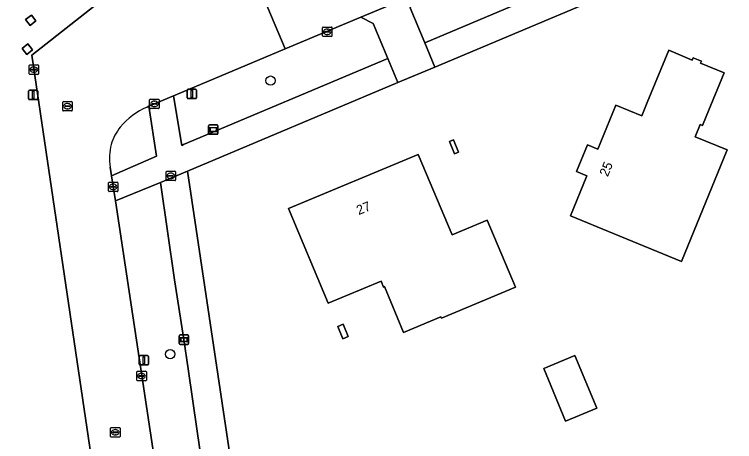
# Model space of a CAD drawing. Extents: x 162417 to 163722, y 384268 to 385417.
# Drawn here: x 163157.7 to 163233.6, y 384866.4 to 384911.4 of the extents above; entities that cross this region are included whole.
import ezdxf

# ---------------------------------------------------------------- set-up
doc = ezdxf.new("R2010")
doc.units = 0
for name, color, linetype in [('IMGEO_Berm_groen', 7, 'Continuous'), ('IMGEO_Boom', 7, 'Continuous'), ('IMGEO_Brandkraan', 7, 'Continuous'), ('IMGEO_Erf', 7, 'Continuous'), ('IMGEO_Groenvoorziening', 7, 'Continuous'), ('IMGEO_Kolk', 7, 'Continuous'), ('IMGEO_Lichtmast', 7, 'Continuous'), ('IMGEO_Pand', 7, 'Continuous'), ('IMGEO_Pand_nummerreeks', 7, 'Continuous'), ('IMGEO_Rijbaan_lokaal_gesloten', 7, 'Continuous'), ('IMGEO_Rioolput', 7, 'Continuous'), ('IMGEO_Voetpad_open', 7, 'Continuous'), ('IMGEO_Wegwijzer', 7, 'Continuous')]:
    doc.layers.add(name, color=color, linetype=linetype)

msp = doc.modelspace()

# ---------------------------------------------------------------- linework, layer by layer
at = {"layer": 'IMGEO_Berm_groen'}
msp.add_lwpolyline([(163177.654, 384862.939), (163176.986, 384867.512), (163176.027, 384874.074), (163175.599, 384877.142), (163174.611, 384883.435), (163173.131, 384893.686), (163168.375, 384891.762), (163181.052, 384807.665)], dxfattribs=at)
at = {"layer": 'IMGEO_Boom'}
for centre in [(163184.731, 384904.423), (163174.147, 384875.612)]:
    msp.add_circle(centre, 0.489, dxfattribs=at)
at = {"layer": 'IMGEO_Brandkraan'}
for p, q in [((163173.795, 384894.892), (163174.647, 384894.892)), ((163173.72, 384893.966), (163173.72, 384894.818)), ((163173.979, 384894.386), (163173.979, 384894.398)), ((163174.417, 384894.349), (163174.019, 384894.349)), ((163174.022, 384894.435), (163174.42, 384894.435)), ((163174.231, 384894.112), (163174.206, 384894.112)), ((163174.208, 384894.672), (163174.233, 384894.672)), ((163174.463, 384894.398), (163174.463, 384894.386)), ((163174.721, 384894.818), (163174.721, 384893.966)), ((163174.647, 384893.892), (163173.795, 384893.892))]:
    msp.add_line(p, q, dxfattribs=at)
for points in [[(163173.795, 384894.892), (163174.647, 384894.892)], [(163173.72, 384893.966), (163173.72, 384894.818)], [(163174.721, 384894.818), (163174.721, 384893.966)], [(163174.647, 384893.892), (163173.795, 384893.892)]]:
    msp.add_lwpolyline(points, dxfattribs=at)
for centre, radius, start, end in [((163173.797, 384894.816), 0.0765, 91.55205, 178.44795), ((163173.797, 384894.816), 0.0765, 91.55205, 178.44795), ((163174.645, 384894.816), 0.0765, 1.55205, 88.44795), ((163174.645, 384894.816), 0.0765, 1.55205, 88.44795), ((163174.019, 384894.395), 0.0403, 85.87752, 175.75265), ((163174.016, 384894.385), 0.0366, 178.93798, 274.71019), ((163174.42, 384894.392), 0.043, 264.86636, 352.45326), ((163174.424, 384894.397), 0.0386, 1.73085, 96.63898), ((163173.797, 384893.968), 0.0765, 181.55205, 268.44795), ((163173.797, 384893.968), 0.0765, 181.55205, 268.44795), ((163174.645, 384893.968), 0.0765, 271.55205, 358.44795), ((163174.645, 384893.968), 0.0765, 271.55205, 358.44795)]:
    msp.add_arc(centre, radius, start, end, dxfattribs=at)
for centre, major_axis, ratio, start_param, end_param in [((163174.207, 384894.392), (-0.387, 0.002), 0.722429, 4.712389, 7.853982), ((163174.232, 384894.392), (-0.39, 0.002), 0.717154, 1.570796, 4.712389)]:
    msp.add_ellipse(centre, major_axis=major_axis, ratio=ratio, start_param=start_param, end_param=end_param, dxfattribs=at)
at = {"layer": 'IMGEO_Erf'}
msp.add_lwpolyline([(163355.108, 384922.849), (163338.205, 384963.202), (163332.037, 384960.636), (163331.845, 384960.556), (163328.115, 384959.004), (163309.804, 384951.385), (163305.952, 384950.098), (163301.519, 384948.918), (163287.113, 384942.953), (163279.759, 384939.573), (163273.176, 384936.418), (163263.164, 384931.62), (163230.9, 384918.02), (163227.943, 384916.773), (163202.03, 384905.85), (163198.14, 384904.21), (163175.984, 384894.871), (163189.317, 384805.604)], dxfattribs=at)
for points in [[(163159.564, 384907.094), (163168.293, 384913.998), (163151.904, 384951.836), (163097.149, 384943.131), (163103.623, 384899.24), (163109.03, 384862.7), (163116.803, 384810.173), (163172.668, 384818.516)], [(163160.001, 384910.711), (163159.521, 384911.33), (163158.908, 384910.853), (163159.388, 384910.235)], [(163158.908, 384910.853), (163159.521, 384911.33), (163160.001, 384910.711), (163159.388, 384910.235)], [(163159.639, 384907.669), (163159.149, 384908.282), (163158.541, 384907.796), (163159.031, 384907.183)], [(163158.541, 384907.796), (163159.149, 384908.282), (163159.639, 384907.669), (163159.031, 384907.183)], [(163219.212, 384897.218), (163221.117, 384901.842), (163223.845, 384900.717), (163224.418, 384902.108), (163226.688, 384907.618), (163229.166, 384906.596), (163229.267, 384906.841), (163230.138, 384906.482), (163230.053, 384906.278), (163232.528, 384905.258), (163230.623, 384900.636), (163230.24, 384899.706), (163230.013, 384899.799), (163229.485, 384898.518), (163232.864, 384897.126), (163228.023, 384885.379), (163220.95, 384888.293), (163216.327, 384890.198), (163218.057, 384894.399), (163216.97, 384894.847), (163218.13, 384897.663)], [(163204.002, 384898.194), (163204.551, 384896.897), (163204.113, 384896.72), (163203.576, 384898.018)], [(163207.571, 384889.719), (163210.531, 384882.668), (163202.73, 384879.41), (163202.676, 384879.54), (163198.744, 384877.898), (163196.747, 384882.732), (163196.636, 384882.685), (163196.371, 384883.306), (163190.802, 384880.971), (163186.632, 384890.943), (163200.299, 384896.652), (163203.868, 384888.194)], [(163192.363, 384878.77), (163192.905, 384877.463), (163192.36, 384877.237), (163191.817, 384878.544)], [(163216.811, 384875.464), (163219.102, 384869.919), (163215.802, 384868.554), (163213.511, 384874.1)]]:
    msp.add_lwpolyline(points, close=True, dxfattribs=at)
at = {"layer": 'IMGEO_Groenvoorziening'}
for points in [[(163200.97, 384908.409), (163226.912, 384919.359), (163225.352, 384923.271), (163224.3, 384923.826), (163200.018, 384913.546), (163199.446, 384912.087)], [(163197.077, 384906.757), (163195.54, 384910.438), (163194.231, 384911.102), (163186.272, 384907.759), (163174.684, 384902.892), (163174.507, 384902.818), (163175.359, 384897.603), (163175.545, 384897.682)]]:
    msp.add_lwpolyline(points, close=True, dxfattribs=at)
for points in [[(163167.833, 384895.326), (163167.974, 384894.412), (163172.706, 384896.469), (163171.894, 384901.719)], [(163171.894, 384901.719), (163171.712, 384901.639)]]:
    msp.add_lwpolyline(points, dxfattribs=at)
for centre, radius, start, end in [((163174.631, 384894.765), 7.468, 113.00878, 140.25543), ((163172.938, 384896.273), 5.202, 141.10387, 164.00436), ((163173.401, 384896.276), 5.649, 165.32083, 189.67709)]:
    msp.add_arc(centre, radius, start, end, dxfattribs=at)
at = {"layer": 'IMGEO_Kolk'}
for p, q in [((163190.276, 384910.068), (163191.128, 384910.068)), ((163190.201, 384909.142), (163190.201, 384909.994)), ((163190.46, 384909.562), (163190.46, 384909.574)), ((163190.898, 384909.525), (163190.5, 384909.525)), ((163190.503, 384909.611), (163190.901, 384909.611)), ((163190.712, 384909.288), (163190.687, 384909.288)), ((163190.689, 384909.848), (163190.714, 384909.848)), ((163190.944, 384909.574), (163190.944, 384909.562)), ((163191.202, 384909.994), (163191.202, 384909.142)), ((163191.128, 384909.068), (163190.276, 384909.068)), ((163159.282, 384905.156), (163159.282, 384906.008)), ((163159.357, 384906.082), (163160.209, 384906.082)), ((163159.541, 384905.576), (163159.541, 384905.588)), ((163159.979, 384905.539), (163159.581, 384905.539)), ((163159.584, 384905.625), (163159.982, 384905.625)), ((163159.77, 384905.862), (163159.795, 384905.862)), ((163160.025, 384905.588), (163160.025, 384905.576)), ((163160.283, 384906.008), (163160.283, 384905.156)), ((163160.209, 384905.082), (163159.357, 384905.082)), ((163159.793, 384905.302), (163159.768, 384905.302)), ((163172.058, 384902.474), (163172.91, 384902.474)), ((163171.983, 384901.548), (163171.983, 384902.4)), ((163172.242, 384901.968), (163172.242, 384901.98)), ((163172.68, 384901.931), (163172.282, 384901.931)), ((163172.285, 384902.017), (163172.683, 384902.017)), ((163172.494, 384901.694), (163172.469, 384901.694)), ((163172.471, 384902.254), (163172.496, 384902.254)), ((163172.726, 384901.98), (163172.726, 384901.968)), ((163172.984, 384902.4), (163172.984, 384901.548)), ((163172.91, 384901.474), (163172.058, 384901.474)), ((163167.645, 384892.808), (163167.645, 384893.66)), ((163167.72, 384893.734), (163168.572, 384893.734)), ((163168.133, 384893.514), (163168.158, 384893.514)), ((163168.646, 384893.66), (163168.646, 384892.808)), ((163168.572, 384892.734), (163167.72, 384892.734)), ((163167.904, 384893.228), (163167.904, 384893.24)), ((163168.342, 384893.191), (163167.944, 384893.191)), ((163167.947, 384893.277), (163168.345, 384893.277)), ((163168.156, 384892.954), (163168.131, 384892.954)), ((163168.388, 384893.24), (163168.388, 384893.228)), ((163170.636, 384872.888), (163170.636, 384873.74)), ((163170.711, 384873.814), (163171.563, 384873.814)), ((163171.637, 384873.74), (163171.637, 384872.888)), ((163170.895, 384873.308), (163170.895, 384873.32)), ((163171.333, 384873.271), (163170.935, 384873.271)), ((163170.938, 384873.357), (163171.336, 384873.357)), ((163171.147, 384873.034), (163171.122, 384873.034)), ((163171.124, 384873.594), (163171.149, 384873.594)), ((163171.379, 384873.32), (163171.379, 384873.308)), ((163171.563, 384872.814), (163170.711, 384872.814))]:
    msp.add_line(p, q, dxfattribs=at)
for points in [[(163190.276, 384910.068), (163191.128, 384910.068)], [(163190.201, 384909.142), (163190.201, 384909.994)], [(163191.202, 384909.994), (163191.202, 384909.142)], [(163191.128, 384909.068), (163190.276, 384909.068)], [(163159.282, 384905.156), (163159.282, 384906.008)], [(163159.357, 384906.082), (163160.209, 384906.082)], [(163160.283, 384906.008), (163160.283, 384905.156)], [(163160.209, 384905.082), (163159.357, 384905.082)], [(163172.058, 384902.474), (163172.91, 384902.474)], [(163171.983, 384901.548), (163171.983, 384902.4)], [(163172.984, 384902.4), (163172.984, 384901.548)], [(163172.91, 384901.474), (163172.058, 384901.474)], [(163167.645, 384892.808), (163167.645, 384893.66)], [(163167.72, 384893.734), (163168.572, 384893.734)], [(163168.646, 384893.66), (163168.646, 384892.808)], [(163168.572, 384892.734), (163167.72, 384892.734)], [(163170.636, 384872.888), (163170.636, 384873.74)], [(163170.711, 384873.814), (163171.563, 384873.814)], [(163171.637, 384873.74), (163171.637, 384872.888)], [(163171.563, 384872.814), (163170.711, 384872.814)]]:
    msp.add_lwpolyline(points, dxfattribs=at)
for centre, radius, start, end in [((163190.278, 384909.992), 0.0765, 91.55205, 178.44795), ((163190.278, 384909.992), 0.0765, 91.55205, 178.44795), ((163191.126, 384909.992), 0.0765, 1.55205, 88.44795), ((163191.126, 384909.992), 0.0765, 1.55205, 88.44795), ((163190.5, 384909.571), 0.0403, 85.87752, 175.75265), ((163190.497, 384909.561), 0.0366, 178.93798, 274.71019), ((163190.901, 384909.568), 0.043, 264.86636, 352.45326), ((163190.905, 384909.573), 0.0386, 1.73085, 96.63898), ((163190.278, 384909.144), 0.0765, 181.55205, 268.44795), ((163190.278, 384909.144), 0.0765, 181.55205, 268.44795), ((163191.126, 384909.144), 0.0765, 271.55205, 358.44795), ((163191.126, 384909.144), 0.0765, 271.55205, 358.44795), ((163159.359, 384906.006), 0.0765, 91.55205, 178.44795), ((163159.359, 384906.006), 0.0765, 91.55205, 178.44795), ((163159.581, 384905.585), 0.0403, 85.87752, 175.75265), ((163159.578, 384905.575), 0.0366, 178.93798, 274.71019), ((163159.982, 384905.582), 0.043, 264.86636, 352.45326), ((163159.986, 384905.587), 0.0386, 1.73085, 96.63898), ((163160.207, 384906.006), 0.0765, 1.55205, 88.44795), ((163160.207, 384906.006), 0.0765, 1.55205, 88.44795), ((163159.359, 384905.158), 0.0765, 181.55205, 268.44795), ((163159.359, 384905.158), 0.0765, 181.55205, 268.44795), ((163160.207, 384905.158), 0.0765, 271.55205, 358.44795), ((163160.207, 384905.158), 0.0765, 271.55205, 358.44795), ((163172.06, 384902.398), 0.0765, 91.55205, 178.44795), ((163172.06, 384902.398), 0.0765, 91.55205, 178.44795), ((163172.908, 384902.398), 0.0765, 1.55205, 88.44795), ((163172.908, 384902.398), 0.0765, 1.55205, 88.44795), ((163172.282, 384901.977), 0.0403, 85.87752, 175.75265), ((163172.279, 384901.967), 0.0366, 178.93798, 274.71019), ((163172.683, 384901.974), 0.043, 264.86636, 352.45326), ((163172.687, 384901.979), 0.0386, 1.73085, 96.63898), ((163172.06, 384901.55), 0.0765, 181.55205, 268.44795), ((163172.06, 384901.55), 0.0765, 181.55205, 268.44795), ((163172.908, 384901.55), 0.0765, 271.55205, 358.44795), ((163172.908, 384901.55), 0.0765, 271.55205, 358.44795), ((163167.722, 384893.658), 0.0765, 91.55205, 178.44795), ((163167.722, 384893.658), 0.0765, 91.55205, 178.44795), ((163168.57, 384893.658), 0.0765, 1.55205, 88.44795), ((163168.57, 384893.658), 0.0765, 1.55205, 88.44795), ((163167.722, 384892.81), 0.0765, 181.55205, 268.44795), ((163167.722, 384892.81), 0.0765, 181.55205, 268.44795), ((163167.944, 384893.237), 0.0403, 85.87752, 175.75265), ((163167.941, 384893.227), 0.0366, 178.93798, 274.71019), ((163168.345, 384893.234), 0.043, 264.86636, 352.45326), ((163168.349, 384893.239), 0.0386, 1.73085, 96.63898), ((163168.57, 384892.81), 0.0765, 271.55205, 358.44795), ((163168.57, 384892.81), 0.0765, 271.55205, 358.44795), ((163170.713, 384873.738), 0.0765, 91.55205, 178.44795), ((163170.713, 384873.738), 0.0765, 91.55205, 178.44795), ((163171.561, 384873.738), 0.0765, 1.55205, 88.44795), ((163171.561, 384873.738), 0.0765, 1.55205, 88.44795), ((163170.713, 384872.89), 0.0765, 181.55205, 268.44795), ((163170.713, 384872.89), 0.0765, 181.55205, 268.44795), ((163170.935, 384873.317), 0.0403, 85.87752, 175.75265), ((163170.932, 384873.307), 0.0366, 178.93798, 274.71019), ((163171.336, 384873.314), 0.043, 264.86636, 352.45326), ((163171.34, 384873.319), 0.0386, 1.73085, 96.63898), ((163171.561, 384872.89), 0.0765, 271.55205, 358.44795), ((163171.561, 384872.89), 0.0765, 271.55205, 358.44795)]:
    msp.add_arc(centre, radius, start, end, dxfattribs=at)
for centre, major_axis, ratio, start_param, end_param in [((163190.688, 384909.568), (-0.387, 0.002), 0.722429, 4.712389, 7.853982), ((163190.713, 384909.568), (-0.39, 0.002), 0.717154, 1.570796, 4.712389), ((163159.769, 384905.582), (-0.387, 0.002), 0.722429, 4.712389, 7.853982), ((163159.794, 384905.582), (-0.39, 0.002), 0.717154, 1.570796, 4.712389), ((163172.47, 384901.974), (-0.387, 0.002), 0.722429, 4.712389, 7.853982), ((163172.495, 384901.974), (-0.39, 0.002), 0.717154, 1.570796, 4.712389), ((163168.132, 384893.234), (-0.387, 0.002), 0.722429, 4.712389, 7.853982), ((163168.157, 384893.234), (-0.39, 0.002), 0.717154, 1.570796, 4.712389), ((163171.123, 384873.314), (-0.387, 0.002), 0.722429, 4.712389, 7.853982), ((163171.148, 384873.314), (-0.39, 0.002), 0.717154, 1.570796, 4.712389)]:
    msp.add_ellipse(centre, major_axis=major_axis, ratio=ratio, start_param=start_param, end_param=end_param, dxfattribs=at)
at = {"layer": 'IMGEO_Lichtmast'}
for p, q in [((163159.221, 384902.524), (163159.221, 384903.324)), ((163159.221, 384903.324), (163159.221, 384902.524)), ((163159.321, 384903.424), (163160.111, 384903.424)), ((163160.111, 384903.424), (163159.321, 384903.424)), ((163160.211, 384903.324), (163160.211, 384902.524)), ((163160.211, 384902.524), (163160.211, 384903.324)), ((163175.937, 384902.627), (163175.937, 384903.427)), ((163175.937, 384903.427), (163175.937, 384902.627)), ((163176.037, 384903.527), (163176.827, 384903.527)), ((163176.827, 384903.527), (163176.037, 384903.527)), ((163176.927, 384903.427), (163176.927, 384902.627)), ((163176.927, 384902.627), (163176.927, 384903.427)), ((163176.827, 384902.527), (163176.037, 384902.527)), ((163176.037, 384902.527), (163176.827, 384902.527)), ((163160.111, 384902.424), (163159.321, 384902.424)), ((163159.321, 384902.424), (163160.111, 384902.424)), ((163170.877, 384874.574), (163170.877, 384875.374)), ((163170.877, 384875.374), (163170.877, 384874.574)), ((163170.977, 384875.474), (163171.767, 384875.474)), ((163171.767, 384875.474), (163170.977, 384875.474)), ((163171.867, 384875.374), (163171.867, 384874.574)), ((163171.867, 384874.574), (163171.867, 384875.374)), ((163171.767, 384874.474), (163170.977, 384874.474)), ((163170.977, 384874.474), (163171.767, 384874.474))]:
    msp.add_line(p, q, dxfattribs=at)
for points in [[(163159.641, 384903.299), (163159.791, 384903.299), (163159.791, 384902.549), (163159.641, 384902.549), (163159.641, 384903.299)], [(163176.357, 384903.402), (163176.507, 384903.402), (163176.507, 384902.652), (163176.357, 384902.652), (163176.357, 384903.402)], [(163171.297, 384875.349), (163171.447, 384875.349), (163171.447, 384874.599), (163171.297, 384874.599), (163171.297, 384875.349)]]:
    msp.add_lwpolyline(points, dxfattribs=at)
for centre, start, end in [((163159.321, 384903.324), 90, 180), ((163159.321, 384903.324), 90, 180), ((163160.111, 384903.324), 0, 90), ((163160.111, 384903.324), 360, 90), ((163176.037, 384903.427), 90, 180), ((163176.037, 384903.427), 90, 180), ((163176.827, 384903.427), 0, 90), ((163176.827, 384903.427), 360, 90), ((163159.321, 384902.524), 180, 270), ((163159.321, 384902.524), 180, 270), ((163160.111, 384902.524), 270, 0), ((163160.111, 384902.524), 270, 0), ((163176.037, 384902.627), 180, 270), ((163176.037, 384902.627), 180, 270), ((163176.827, 384902.627), 270, 0), ((163176.827, 384902.627), 270, 0), ((163170.977, 384875.374), 90, 180), ((163170.977, 384875.374), 90, 180), ((163171.767, 384875.374), 0, 90), ((163171.767, 384875.374), 360, 90), ((163170.977, 384874.574), 180, 270), ((163170.977, 384874.574), 180, 270), ((163171.767, 384874.574), 270, 0), ((163171.767, 384874.574), 270, 0)]:
    msp.add_arc(centre, 0.1, start, end, dxfattribs=at)
at = {"layer": 'IMGEO_Pand'}
for points in [[(163219.212, 384897.218), (163218.13, 384897.663), (163216.97, 384894.847), (163218.057, 384894.399), (163216.327, 384890.198), (163220.95, 384888.293), (163228.023, 384885.379), (163232.864, 384897.126), (163229.485, 384898.518), (163230.013, 384899.799), (163230.24, 384899.706), (163230.623, 384900.636), (163232.528, 384905.258), (163230.053, 384906.278), (163230.138, 384906.482), (163229.267, 384906.841), (163229.166, 384906.596), (163226.688, 384907.618), (163224.418, 384902.108), (163223.845, 384900.717), (163221.117, 384901.842)], [(163204.002, 384898.194), (163203.576, 384898.018), (163204.113, 384896.72), (163204.551, 384896.897)], [(163207.571, 384889.719), (163203.868, 384888.194), (163200.299, 384896.652), (163186.632, 384890.943), (163190.802, 384880.971), (163196.371, 384883.306), (163196.636, 384882.685), (163196.747, 384882.732), (163198.744, 384877.898), (163202.676, 384879.54), (163202.73, 384879.41), (163210.531, 384882.668)], [(163192.363, 384878.77), (163191.817, 384878.544), (163192.36, 384877.237), (163192.905, 384877.463)], [(163216.811, 384875.464), (163213.511, 384874.1), (163215.802, 384868.554), (163219.102, 384869.919)]]:
    msp.add_lwpolyline(points, close=True, dxfattribs=at)
at = {"layer": 'IMGEO_Rijbaan_lokaal_gesloten'}
for points in [[(163337.564, 384978.789), (163336.54, 384978.154), (163336.199, 384978.01), (163333.911, 384977.041), (163328.962, 384974.963), (163183.667, 384913.961), (163186.272, 384907.759), (163194.231, 384911.102), (163200.018, 384913.546), (163224.3, 384923.826)], [(163186.272, 384907.759), (163183.667, 384913.961), (163175.758, 384919.851), (163175.467, 384919.624), (163173.108, 384917.782), (163170.764, 384915.952), (163168.293, 384913.998), (163159.564, 384907.094), (163172.668, 384818.516)], [(163171.712, 384901.639), (163171.894, 384901.719), (163172.075, 384901.798), (163174.507, 384902.818), (163174.684, 384902.892), (163186.272, 384907.759)], [(163181.052, 384807.665), (163168.375, 384891.762), (163167.974, 384894.412), (163167.833, 384895.326)]]:
    msp.add_lwpolyline(points, dxfattribs=at)
for centre, radius, start, end in [((163174.631, 384894.765), 7.468, 113.00878, 140.25543), ((163172.938, 384896.273), 5.202, 141.10387, 164.00436), ((163173.401, 384896.276), 5.649, 165.32083, 189.67709)]:
    msp.add_arc(centre, radius, start, end, dxfattribs=at)
at = {"layer": 'IMGEO_Rioolput'}
for p, q in [((163162.823, 384901.302), (163162.823, 384902.154)), ((163162.898, 384902.228), (163163.75, 384902.228)), ((163163.082, 384901.722), (163163.082, 384901.734)), ((163163.52, 384901.685), (163163.122, 384901.685)), ((163163.125, 384901.771), (163163.523, 384901.771)), ((163163.311, 384902.008), (163163.336, 384902.008)), ((163163.566, 384901.734), (163163.566, 384901.722)), ((163163.824, 384902.154), (163163.824, 384901.302)), ((163163.75, 384901.228), (163162.898, 384901.228)), ((163163.334, 384901.448), (163163.309, 384901.448)), ((163167.865, 384866.958), (163167.865, 384867.81)), ((163167.94, 384867.884), (163168.792, 384867.884)), ((163168.353, 384867.664), (163168.378, 384867.664)), ((163168.866, 384867.81), (163168.866, 384866.958)), ((163168.792, 384866.884), (163167.94, 384866.884)), ((163168.124, 384867.378), (163168.124, 384867.39)), ((163168.562, 384867.341), (163168.164, 384867.341)), ((163168.167, 384867.427), (163168.565, 384867.427)), ((163168.376, 384867.104), (163168.351, 384867.104)), ((163168.608, 384867.39), (163168.608, 384867.378))]:
    msp.add_line(p, q, dxfattribs=at)
for points in [[(163162.823, 384901.302), (163162.823, 384902.154)], [(163162.898, 384902.228), (163163.75, 384902.228)], [(163163.824, 384902.154), (163163.824, 384901.302)], [(163163.75, 384901.228), (163162.898, 384901.228)], [(163167.865, 384866.958), (163167.865, 384867.81)], [(163167.94, 384867.884), (163168.792, 384867.884)], [(163168.866, 384867.81), (163168.866, 384866.958)], [(163168.792, 384866.884), (163167.94, 384866.884)]]:
    msp.add_lwpolyline(points, dxfattribs=at)
for centre, radius, start, end in [((163162.9, 384902.152), 0.0765, 91.55205, 178.44795), ((163162.9, 384902.152), 0.0765, 91.55205, 178.44795), ((163163.122, 384901.731), 0.0403, 85.87752, 175.75265), ((163163.119, 384901.721), 0.0366, 178.93798, 274.71019), ((163163.523, 384901.728), 0.043, 264.86636, 352.45326), ((163163.527, 384901.733), 0.0386, 1.73085, 96.63898), ((163163.748, 384902.152), 0.0765, 1.55205, 88.44795), ((163163.748, 384902.152), 0.0765, 1.55205, 88.44795), ((163162.9, 384901.304), 0.0765, 181.55205, 268.44795), ((163162.9, 384901.304), 0.0765, 181.55205, 268.44795), ((163163.748, 384901.304), 0.0765, 271.55205, 358.44795), ((163163.748, 384901.304), 0.0765, 271.55205, 358.44795), ((163167.942, 384867.808), 0.0765, 91.55205, 178.44795), ((163167.942, 384867.808), 0.0765, 91.55205, 178.44795), ((163168.79, 384867.808), 0.0765, 1.55205, 88.44795), ((163168.79, 384867.808), 0.0765, 1.55205, 88.44795), ((163167.942, 384866.96), 0.0765, 181.55205, 268.44795), ((163167.942, 384866.96), 0.0765, 181.55205, 268.44795), ((163168.164, 384867.387), 0.0403, 85.87752, 175.75265), ((163168.161, 384867.377), 0.0366, 178.93798, 274.71019), ((163168.565, 384867.384), 0.043, 264.86636, 352.45326), ((163168.569, 384867.389), 0.0386, 1.73085, 96.63898), ((163168.79, 384866.96), 0.0765, 271.55205, 358.44795), ((163168.79, 384866.96), 0.0765, 271.55205, 358.44795)]:
    msp.add_arc(centre, radius, start, end, dxfattribs=at)
for centre, major_axis, ratio, start_param, end_param in [((163163.31, 384901.728), (-0.387, 0.002), 0.722429, 4.712389, 7.853982), ((163163.335, 384901.728), (-0.39, 0.002), 0.717154, 1.570796, 4.712389), ((163168.352, 384867.384), (-0.387, 0.002), 0.722429, 4.712389, 7.853982), ((163168.377, 384867.384), (-0.39, 0.002), 0.717154, 1.570796, 4.712389)]:
    msp.add_ellipse(centre, major_axis=major_axis, ratio=ratio, start_param=start_param, end_param=end_param, dxfattribs=at)
at = {"layer": 'IMGEO_Voetpad_open'}
for points in [[(163202.03, 384905.85), (163227.943, 384916.773), (163226.912, 384919.359), (163200.97, 384908.409)], [(163200.97, 384908.409), (163199.446, 384912.087), (163200.018, 384913.546), (163194.231, 384911.102), (163195.54, 384910.438), (163197.077, 384906.757), (163198.14, 384904.21), (163202.03, 384905.85)], [(163198.14, 384904.21), (163197.077, 384906.757), (163175.545, 384897.682), (163175.359, 384897.603), (163174.507, 384902.818), (163172.075, 384901.798), (163171.894, 384901.719), (163172.706, 384896.469), (163167.974, 384894.412), (163168.375, 384891.762), (163173.131, 384893.686), (163175.984, 384894.871)], [(163175.984, 384894.871), (163173.131, 384893.686), (163174.611, 384883.435), (163175.599, 384877.142), (163176.027, 384874.074), (163176.986, 384867.512), (163177.654, 384862.939), (163181.731, 384836.256), (163185.853, 384808.72), (163186.458, 384804.456), (163186.712, 384804.512), (163189.317, 384805.604)]]:
    msp.add_lwpolyline(points, close=True, dxfattribs=at)
at = {"layer": 'IMGEO_Wegwijzer'}
for p, q in [((163178.194, 384898.868), (163178.194, 384899.668)), ((163178.194, 384899.668), (163178.194, 384898.868)), ((163178.294, 384899.768), (163179.084, 384899.768)), ((163179.084, 384899.768), (163178.294, 384899.768)), ((163179.184, 384899.668), (163179.184, 384898.868)), ((163179.184, 384898.868), (163179.184, 384899.668)), ((163179.084, 384898.768), (163178.294, 384898.768)), ((163178.294, 384898.768), (163179.084, 384898.768)), ((163175.104, 384876.742), (163175.104, 384877.542)), ((163175.104, 384877.542), (163175.104, 384876.742)), ((163175.204, 384877.642), (163175.994, 384877.642)), ((163175.994, 384877.642), (163175.204, 384877.642)), ((163176.094, 384877.542), (163176.094, 384876.742)), ((163176.094, 384876.742), (163176.094, 384877.542)), ((163175.994, 384876.642), (163175.204, 384876.642)), ((163175.204, 384876.642), (163175.994, 384876.642))]:
    msp.add_line(p, q, dxfattribs=at)
for points in [[(163178.295, 384899.5), (163179.083, 384899.5), (163179.083, 384899.036), (163178.295, 384899.036), (163178.295, 384899.5)], [(163178.36, 384899.435), (163178.36, 384899.101), (163179.018, 384899.101), (163179.018, 384899.435), (163178.36, 384899.435)], [(163175.205, 384877.374), (163175.993, 384877.374), (163175.993, 384876.91), (163175.205, 384876.91), (163175.205, 384877.374)], [(163175.27, 384877.309), (163175.27, 384876.975), (163175.928, 384876.975), (163175.928, 384877.309), (163175.27, 384877.309)]]:
    msp.add_lwpolyline(points, dxfattribs=at)
for centre, start, end in [((163178.294, 384899.668), 90, 180), ((163178.294, 384899.668), 90, 180), ((163179.084, 384899.668), 0, 90), ((163179.084, 384899.668), 360, 90), ((163178.294, 384898.868), 180, 270), ((163178.294, 384898.868), 180, 270), ((163179.084, 384898.868), 270, 0), ((163179.084, 384898.868), 270, 0), ((163175.204, 384877.542), 90, 180), ((163175.204, 384877.542), 90, 180), ((163175.994, 384877.542), 0, 90), ((163175.994, 384877.542), 360, 90), ((163175.204, 384876.742), 180, 270), ((163175.204, 384876.742), 180, 270), ((163175.994, 384876.742), 270, 0), ((163175.994, 384876.742), 270, 0)]:
    msp.add_arc(centre, 0.1, start, end, dxfattribs=at)

# ---------------------------------------------------------------- texts
at = {"layer": 'IMGEO_Pand_nummerreeks'}
for s, rotation, p in [('25', 67.61168, (163220.267, 384894.241)), ('27', 22.35681, (163194.017, 384890.255))]:
    msp.add_text(s, height=1, rotation=rotation, dxfattribs=at).set_placement(p)

doc.saveas('drawing.dxf')
